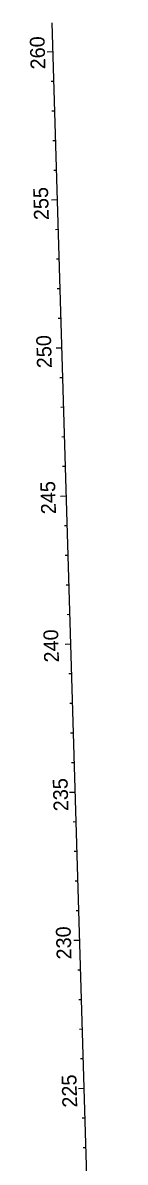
# Model space of a CAD drawing. Extents: x 448091 to 665917, y 1461380 to 1587607.
# Drawn here: x 477133 to 477433, y 1544068 to 1547913 of the extents above; entities that cross this region are included whole.
import ezdxf

# ---------------------------------------------------------------- set-up
doc = ezdxf.new("R2010")
doc.units = 0
doc.layers.add('TextShtNo', color=7, linetype='Continuous')
doc.layers.add('TextTitle', color=7, linetype='Continuous')

msp = doc.modelspace()

# ---------------------------------------------------------------- linework, layer by layer
at = {"layer": 'TextShtNo'}
for p, q in [((477215.2, 1547724.6), (477209.5, 1547913.4)), ((477433.1, 1540487.3), (477215.2, 1547724.6))]:
    msp.add_line(p, q, dxfattribs=at)
at = {"layer": 'TextTitle'}
for p, q in [((477212.8, 1547815.1), (477192.5, 1547814.6)), ((477215.5, 1547715.1), (477205.5, 1547714.8)), ((477218.5, 1547615.1), (477208.5, 1547614.8)), ((477221.5, 1547515.2), (477211.5, 1547514.9)), ((477224.5, 1547415.2), (477214.5, 1547414.9)), ((477227.5, 1547315.3), (477207.5, 1547314.7)), ((477230.5, 1547215.3), (477220.6, 1547215)), ((477233.6, 1547115.4), (477223.6, 1547115.1)), ((477236.6, 1547015.4), (477226.6, 1547015.1)), ((477239.6, 1546915.5), (477229.6, 1546915.2)), ((477242.6, 1546815.5), (477222.6, 1546814.9)), ((477245.6, 1546715.5), (477235.6, 1546715.2)), ((477248.6, 1546615.6), (477238.6, 1546615.3)), ((477251.6, 1546515.6), (477241.6, 1546515.3)), ((477254.6, 1546415.7), (477244.6, 1546415.4)), ((477257.6, 1546315.7), (477237.6, 1546315.1)), ((477260.6, 1546215.8), (477250.6, 1546215.5)), ((477263.6, 1546115.8), (477253.7, 1546115.5)), ((477266.7, 1546015.9), (477256.7, 1546015.6)), ((477269.7, 1545915.9), (477259.7, 1545915.6)), ((477272.7, 1545815.9), (477252.7, 1545815.3)), ((477275.7, 1545716), (477265.7, 1545715.7)), ((477278.7, 1545616), (477268.7, 1545615.7)), ((477281.7, 1545516.1), (477271.7, 1545515.8)), ((477284.7, 1545416.1), (477274.7, 1545415.8)), ((477287.7, 1545316.2), (477267.7, 1545315.6)), ((477290.7, 1545216.2), (477280.7, 1545215.9)), ((477293.7, 1545116.3), (477283.7, 1545116)), ((477296.8, 1545016.3), (477286.8, 1545016)), ((477299.8, 1544916.4), (477289.8, 1544916.1)), ((477302.8, 1544816.4), (477282.8, 1544815.8)), ((477305.8, 1544716.4), (477295.8, 1544716.1)), ((477308.8, 1544616.5), (477298.8, 1544616.2)), ((477311.8, 1544516.5), (477301.8, 1544516.2)), ((477314.8, 1544416.6), (477304.8, 1544416.3)), ((477317.8, 1544316.6), (477297.8, 1544316)), ((477320.8, 1544216.7), (477310.8, 1544216.4)), ((477323.8, 1544116.7), (477313.8, 1544116.4))]:
    msp.add_line(p, q, dxfattribs=at)

# ---------------------------------------------------------------- texts
for s, p in [('260', (477186.6, 1547756.9)), ('255', (477198.2, 1547248.1)), ('250', (477208.3, 1546748.4)), ('245', (477222.3, 1546255.7)), ('240', (477232.4, 1545755.4)), ('235', (477264.3, 1545253.2)), ('230', (477274.7, 1544753.1)), ('225', (477294.1, 1544253.1))]:
    msp.add_text(s, height=50, rotation=91.7245, dxfattribs=at).set_placement(p)

doc.saveas('drawing.dxf')
